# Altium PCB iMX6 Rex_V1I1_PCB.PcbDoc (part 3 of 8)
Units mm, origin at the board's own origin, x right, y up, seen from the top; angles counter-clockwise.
Board outline 70 x 40 mm, 12 copper layers (L1, L2, L3, L4, L5 (PWR), L6 (PWR), L7 (PWR), L8 (PWR), L9, L10, L11, L12), stack 1.566 mm thick; 473 components, 409 nets, 2294 pads, 1880 vias.
Unrouted connection lines stored in the file: 7.
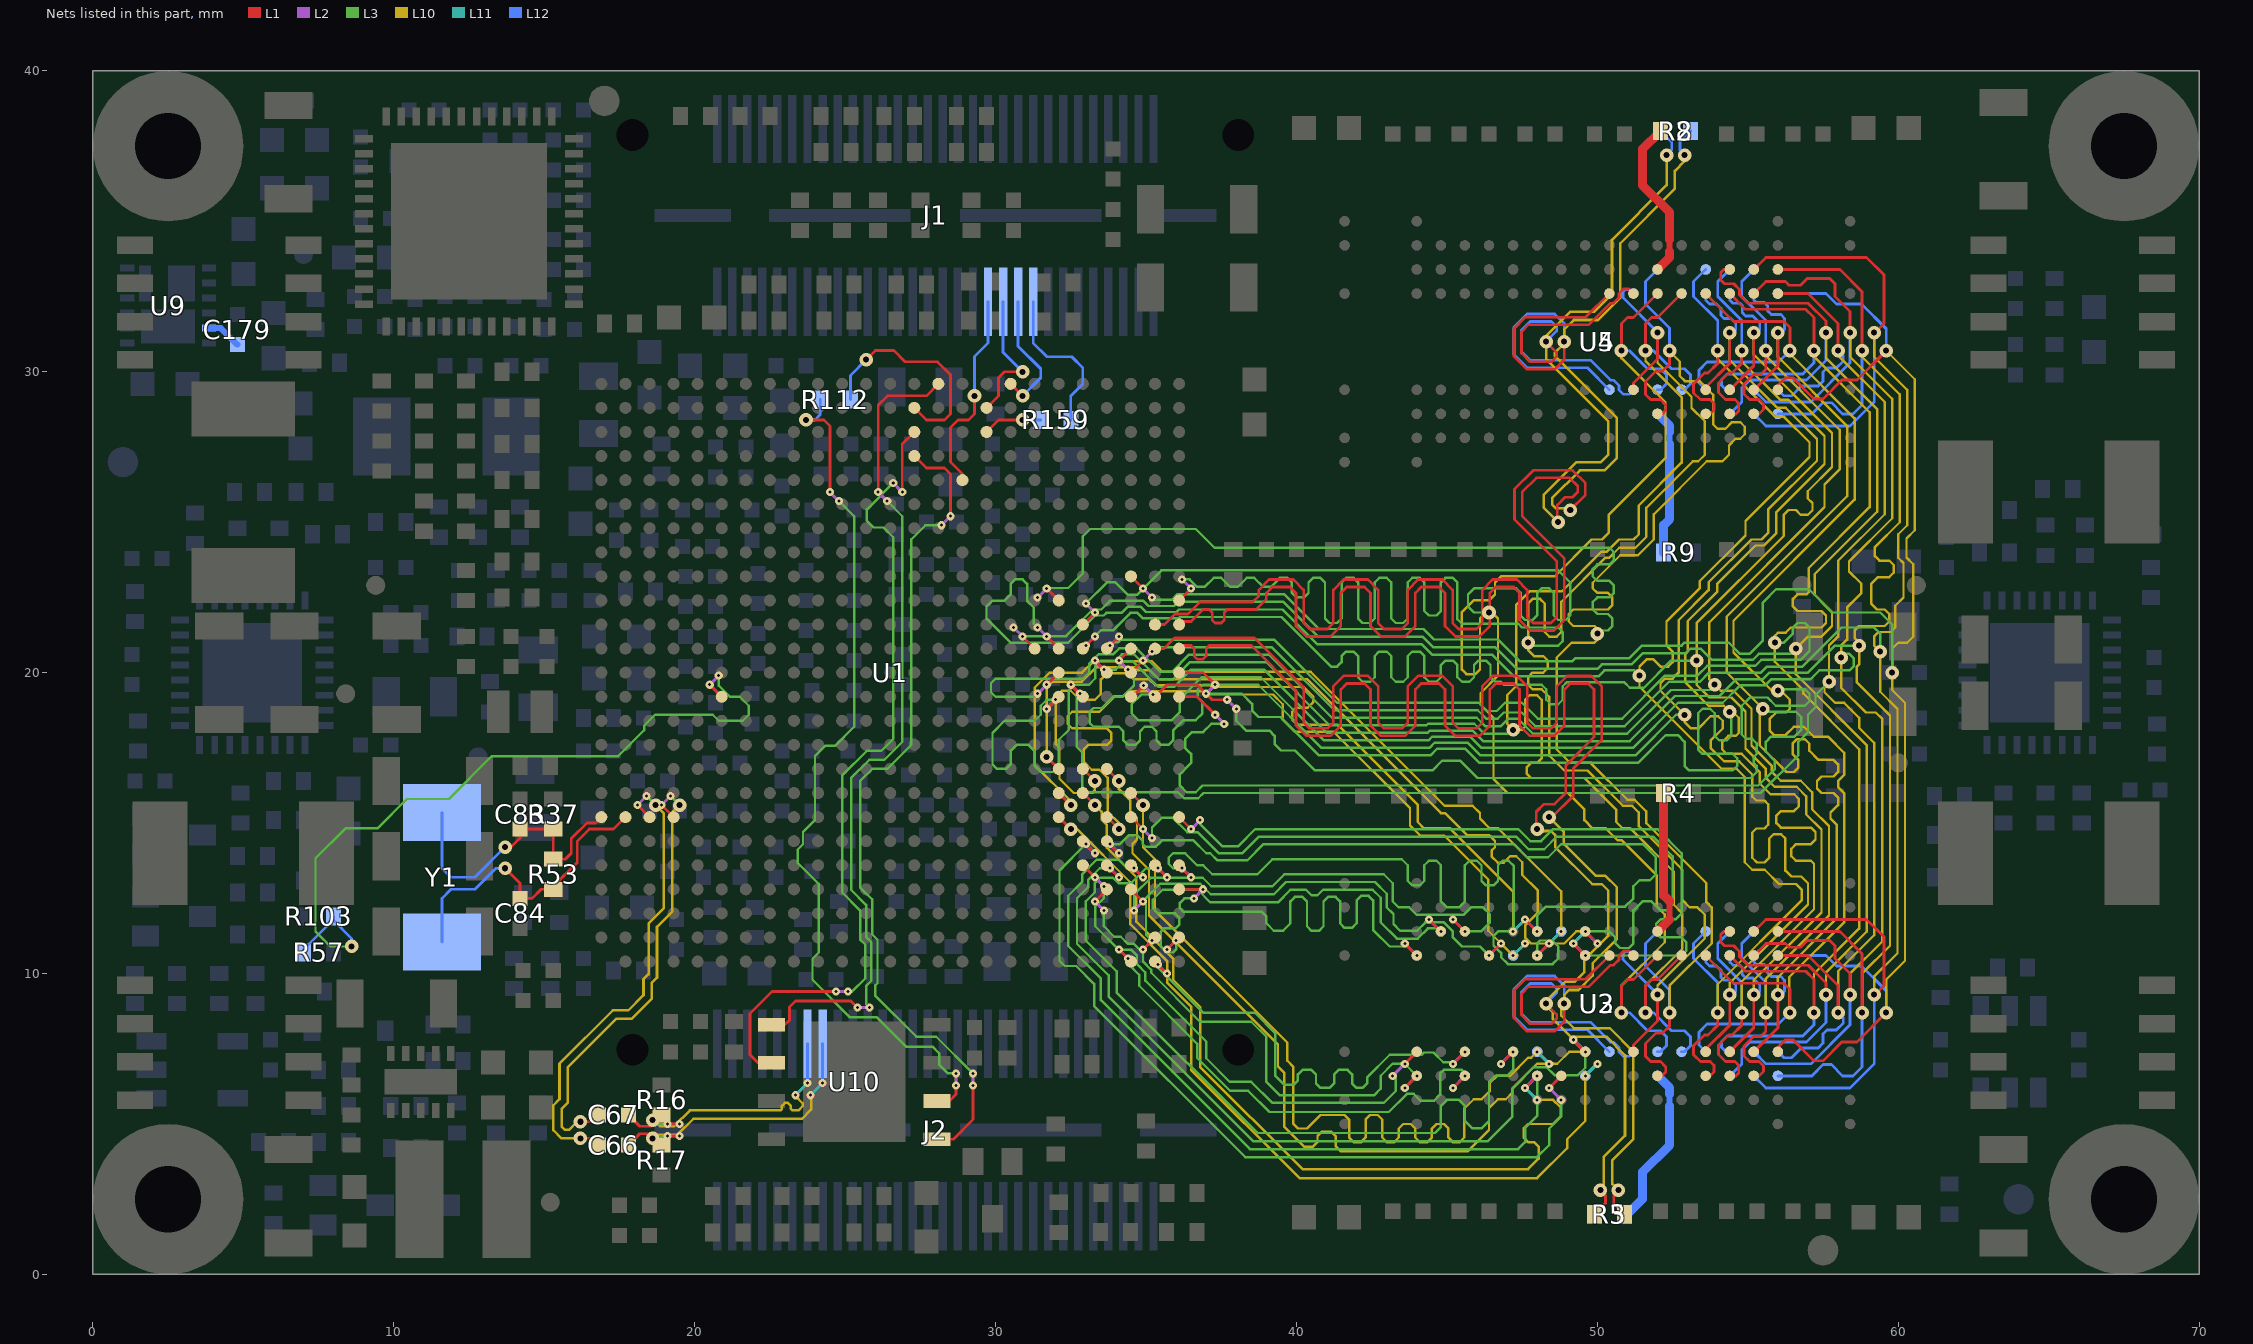
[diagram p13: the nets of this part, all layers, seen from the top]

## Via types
v1: diameter 0.45, hole 0.2, L1 to L12, tented both sides, 761 vias
v2: diameter 0.27, hole 0.1, L1 to L2, 305 vias
v3: diameter 0.27, hole 0.1, L2 to L3, 290 vias
v4: diameter 0.45, hole 0.2, L3 to L10, 196 vias
v5: diameter 0.27, hole 0.1, L11 to L12, 185 vias
v6: diameter 0.27, hole 0.1, L10 to L11, 142 vias
v7: diameter 0.45, hole 0.2, L3 to L10, tented both sides, 1 vias

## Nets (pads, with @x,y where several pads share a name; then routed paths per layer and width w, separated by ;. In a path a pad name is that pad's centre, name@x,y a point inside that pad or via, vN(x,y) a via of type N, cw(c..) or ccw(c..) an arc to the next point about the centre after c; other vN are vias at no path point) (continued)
BOOT_MODE1: R57.2 R103.1 U1.F12 | length 26.1
  L1 w0.093: v2(20.5,19.6) U1.F12@20.9,19.2
  L2 w0.1: v2(20.5,19.6) v3(20.8,19.9)
  L3 w0.08: v1(8.6,10.9) 7.9,10.9 7.4,11.4 7.4,13.83 8.395,14.825 9.455,14.825 10.43,15.8 11.831,15.8 13.256,17.225 17.461,17.225 18.325,18.089 18.325,18.238 18.687,18.6 20.6,18.6 20.8,18.4 21.6,18.4 21.8,18.6 21.8,18.9 21.5,19.2 21.17,19.2 20.8,19.57 v3(20.8,19.9)
  L12 w0.093: R57.2@7,10.7 7,10.8 R103.1@8,11.8 ; R103.1@8,11.9 R103.1@8,11.8 ; v1(8.6,10.9) 8.6,11.17 8,11.77 R103.1@8,11.8
CFF: C179.2 U9.11 | length 1.2
  L12 w0.2: U9.11@3.86,31.45 4.25,31.45 C179.2@4.8,30.9
CLK1_C_N: C66.1 U1.C7 | length 15.9
  L1 w0.09: v1(16.2,4.525) 16.575,4.525 C66.1@16.8,4.3 ; v2(18.1,15.6) U1.C7@18.5,15.2
  L2 w0.1: v2(18.1,15.6) v3(18.4,15.9)
  L3 w0.085: v3(18.4,15.9) v4(18.7,15.6)
  L10 w0.085: v1(16.2,4.525) 15.575,4.525 15.3,4.8 15.3,5.616 15.508,5.824 15.508,7.004 17.284,8.78 17.8,8.78 18.3,9.28 18.3,9.816 18.468,9.983 18.468,11.664 18.97,12.167 18.97,15.33 v4(18.7,15.6)
CLK1_C_P: C67.1 U1.D7 | length 15.8
  L1 w0.09: v1(16.2,5.075) 16.575,5.075 C67.1@16.8,5.3 ; v2(18.9,15.6) U1.D7@19.3,15.2
  L2 w0.1: v2(18.9,15.6) v3(19.2,15.9)
  L3 w0.085: v3(19.2,15.9) v4(19.5,15.6)
  L10 w0.085: v1(16.2,5.075) 16.096,5.075 15.826,4.805 15.691,4.805 15.58,4.916 15.58,5.5 15.788,5.708 15.788,6.888 17.4,8.5 17.916,8.5 18.58,9.164 18.58,9.7 18.748,9.867 18.748,11.548 19.25,12.051 19.25,15.35 ; 19.25,15.35 v4(19.5,15.6) 19.25,15.35
CLK1_N: C66.2 J2.46 R17.2 | length 11.1
  L1 w0.09: C66.2@17.8,4.3 18.175,4.675 18.525,4.675 R17.2@18.9,4.3 19.2,4.6 v2(19.5,4.6)
  L2 w0.1: v3(19.1,4.6) v2(19.5,4.6)
  L3 w0.085: v4(18.6,4.525) 18.675,4.6 v3(19.1,4.6)
  L10 w0.085: v4(18.6,4.525) 18.725,4.65 19.431,4.65 19.953,5.173 23.568,5.173 23.87,5.474 23.87,5.937 v6(23.85,5.957)
  L11 w0.1: v6(23.85,5.957) v5(24.25,6.358)
  L12 w0.09: v5(24.25,6.358) J2.46@24.25,7.67
CLK1_P: C67.2 J2.48 R16.2 | length 11.1
  L1 w0.09: C67.2@17.8,5.3 18.175,4.925 18.525,4.925 R16.2@18.9,5.3 19.2,5 v2(19.5,5)
  L2 w0.1: v3(19.1,5) v2(19.5,5)
  L3 w0.085: v4(18.6,5.125) 18.725,5 v3(19.1,5)
  L10 w0.085: v4(18.6,5.125) 18.654,5.125 18.849,4.93 19.315,4.93 19.838,5.453 22.853,5.453 22.9,5.5 22.9,5.6 23,5.7 23.1,5.7 23.2,5.6 23.2,5.5 23.247,5.453 23.453,5.453 23.59,5.59 23.59,5.69 23.35,5.931 v6(23.35,5.957)
  L11 w0.1: v6(23.35,5.957) v5(23.75,6.358)
  L12 w0.09: v5(23.75,6.358) J2.48@23.75,7.67
CPU_XTALI: C83.1 R37.1 R53.1 U1.A7 Y1.1 | length 10
  L1 w0.093: v1(13.7,14.2) 13.9,14.2 14.2,14.5 C83.1@14.2,14.8 R37.1@15.3,14.8 R53.1@15.3,13.8 15.7,13.8 15.9,14 15.9,14.483 16.417,15 16.7,15 U1.A7@16.9,15.2
  L12 w0.093: Y1.1@11.6,15.35 11.6,13.5 11.9,13.2 12.7,13.2 v1(13.7,14.2)
CPU_XTALO: C84.1 R53.2 U1.B7 Y1.2 | length 10.2
  L1 w0.093: v1(13.7,13.5) 14.2,13 14.2,12.6 C84.1@14.3,12.6 ; C84.1@14.2,12.5 14.6,12.5 14.9,12.8 R53.2@15.3,12.8 ; R53.2@15.3,12.9 16.1,13.7 16.1,14.4 16.5,14.8 17.3,14.8 U1.B7@17.7,15.2
  L12 w0.093: Y1.2@11.6,11.05 11.6,12.5 11.9,12.8 12.7,12.8 13.4,13.5 v1(13.7,13.5)
CSPI2_CLK: J1.17 R159.2 | length 5.3
  L12 w0.093: J1.17@31.25,32.33 31.25,30.955 31.705,30.5 32.53,30.5 32.9,30.13 32.9,29.6 32.5,29.2 R159.2@32.5,28.4
CSPI2_CLK_R: R159.1 U1.U23 | length 2
  L1 w0.093: U1.U23@29.7,28 30.1,28.4 v1(30.9,28.4)
  L12 w0.093: v1(30.9,28.4) R159.1@31.5,28.4
CSPI2_CS0: J1.19 U1.V25 | length 4.3
  L1 w0.093: U1.V25@30.5,29.6 v1(30.9,29.2)
  L12 w0.093: J1.19@30.75,32.33 30.75,30.85 31.5,30.1 31.5,29.8 v1(30.9,29.2)
CSPI2_MISO: J1.21 U1.U24 | length 4.6
  L1 w0.093: U1.U24@29.7,28.8 30.1,29.2 30.1,29.8 30.3,30 v1(30.9,30)
  L12 w0.093: J1.21@30.25,32.33 30.25,30.65 v1(30.9,30)
CSPI2_MOSI: J1.23 U1.T21 | length 6.8
  L1 w0.093: U1.T21@28.9,26.4 28.9,26.6 28.5,27 28.5,28.15 28.75,28.4 29.1,28.4 29.3,28.6 v1(29.3,29.2)
  L12 w0.093: v1(29.3,29.2) 29.3,30.505 29.75,30.955 J1.23@29.75,32.33
CSPI3_CLK: R112.2 U10.6 | length 29.7
  L1 w0.093: v1(23.7,28.4) 24.3,28.4 24.5,28.2 v2(24.5,26) ; U10.6@28.05,5.765 28.465,5.765 28.688,5.988 v2(28.688,6.28)
  L2 w0.1: v2(24.5,26) v3(24.8,25.7) ; v2(28.688,6.28) v3(28.688,6.68)
  L3 w0.08: v3(24.8,25.7) 25.3,25.2 25.3,18.2 24.675,17.575 24.345,17.575 24,17.23 24,15.1 23.6,14.7 23.6,14.297 23.425,14.122 23.425,13.678 24.125,12.978 24.125,10.7 23.915,10.49 23.915,9.795 25.168,8.543 26.057,8.543 27.027,7.573 27.905,7.573 28.125,7.353 28.125,6.975 28.42,6.68 v3(28.688,6.68)
  L12 w0.093: v1(23.7,28.4) 24,28.4 24.175,28.575 R112.2@24.175,29.075
CSPI3_CLK_R: R112.1 U1.P24 | length 7.6
  L1 w0.093: v1(25.7,30.4) 26.005,30.705 26.625,30.705 27,30.33 28.07,30.33 28.5,29.9 28.5,28.6 28.3,28.4 27.7,28.4 U1.P24@27.3,28.8
  L12 w0.093: R112.1@25.175,29.075 25.175,29.875 v1(25.7,30.4)
CSPI3_CS2: U1.R25 U10.1 | length 28
  L1 w0.093: U10.1@22.55,8.305 23.005,8.305 23.15,8.45 23.15,8.893 23.35,9.093 25.188,9.093 v2(25.413,8.868) ; v2(26.1,26) 26.1,28.895 26.405,29.2 27.7,29.2 U1.R25@28.1,29.6
  L2 w0.1: v2(25.413,8.868) v3(25.812,8.868) ; v2(26.1,26) v3(26.4,25.7)
  L3 w0.08: v3(25.812,8.868) 25.7,8.98 25.7,9.587 25.875,9.762 25.875,11.038 25.7,11.213 25.7,12.283 25.2,12.783 25.2,16.5 25.8,17.1 26.3,17.1 26.9,17.7 26.9,25.2 v3(26.4,25.7)
CSPI3_MISO: U1.P23 U10.2 | length 27.8
  L1 w0.093: U10.2@22.55,7.035 22.107,7.035 21.84,7.302 21.84,8.667 22.573,9.4 v2(24.7,9.4) ; v2(26.9,26) 26.9,27.6 U1.P23@27.3,28
  L2 w0.1: v2(24.7,9.4) v3(25.1,9.4) ; v3(26.6,26.3) v2(26.9,26)
  L3 w0.08: v3(25.1,9.4) 25.23,9.4 25.675,9.845 25.675,10.955 25.5,11.13 25.5,12.1 24.9,12.7 24.9,16.583 25.717,17.4 26.201,17.4 26.6,17.799 26.6,24.5 26.275,24.825 25.945,24.825 25.725,25.045 25.725,25.428 26.597,26.3 v3(26.6,26.3)
CSPI3_MOSI: U1.P22 U10.5 | length 28.2
  L1 w0.093: U1.P22@27.3,27.2 27.7,26.8 28.3,26.8 28.5,26.6 v2(28.5,25.2) ; U10.5@28.05,4.495 28.6,4.495 29.25,5.145 v2(29.25,6.28)
  L2 w0.1: v3(28.2,24.9) v2(28.5,25.2) ; v2(29.25,6.28) v3(29.25,6.68)
  L3 w0.08: v3(28.2,24.9) 27.67,24.9 27.2,24.43 27.2,17.6 26.4,16.8 25.9,16.8 25.5,16.4 25.5,12.866 25.9,12.466 25.9,11.3 26.075,11.125 26.075,9.679 25.998,9.602 25.998,9.272 27.37,7.9 28.03,7.9 v3(29.25,6.68)
DRAM0_ZQ: R4.2 U2.L8 | length 4.8
  L1 w0.2: 52.4,11.8 52.4,12.401
  L1 w0.3: U2.L8@52,11.4 52.4,11.8 ; R4.2@52.2,16 52.2,12.601 52.4,12.401
DRAM1_ZQ: R5.2 U3.L8 | length 5.4
  L12 w0.2: 52.4,5.599 52.4,6.001
  L12 w0.3: R5.2@50.9,2 51,2 51.5,2.5 51.5,3.4 52.4,4.3 52.4,5.599 ; U3.L8@52,6.6 52.4,6.2 52.4,6.001
DRAM2_ZQ: R8.2 U4.L8 | length 5.4
  L1 w0.2: 52.4,33.999 52.4,34.401
  L1 w0.3: U4.L8@52,33.4 52.4,33.8 52.4,33.999 ; R8.2@52.1,38 51.5,37.4 51.5,36.2 52.4,35.3 52.4,34.401
DRAM3_ZQ: R9.2 U5.L8 | length 4.8
  L12 w0.2: 52.4,27.599 52.4,28.001
  L12 w0.3: U5.L8@52,28.6 52.4,28.2 52.4,28.001 ; R9.2@52.2,24 52.2,24.9 52.4,25.1 52.4,27.599
DRAM_A0: U1.AC14 U2.N3 U3.N3 U4.N3 U5.N3 | length 70.8
  L1 w0.093: v2(34.1,20.4) U1.AC14@34.5,20.8 ; U2.N3@53.6,7.4 53.6,7.483 54.4,8.283 v1(54.4,9.3) ; U4.N3@53.6,29.4 53.6,29.483 54.4,30.283 v1(54.4,31.3)
  L2 w0.1: v2(34.1,20.4) v3(34.4,20.1)
  L3 w0.08: v3(34.4,20.1) 34.6,19.9 34.6,19.57 34.23,19.2 33.903,19.2 33.528,18.825 33.25,18.825 33.125,18.7 33.125,18.325 33.25,18.2 34.1,18.2 34.25,18.05 34.25,17.75 34.4,17.6 34.65,17.6 34.8,17.75 34.8,18.05 34.95,18.2 35.2,18.2 35.35,18.05 35.35,17.75 35.5,17.6 35.75,17.6 35.9,17.75 35.9,18.083 36.242,18.425 36.655,18.425 36.875,18.645 36.875,19.022 36.715,19.182 36.715,19.418 36.897,19.6 38.73,19.6 40.83,17.5 44.421,17.5 44.596,17.675 45.687,17.675 46.112,17.25 51.267,17.25 52.617,18.6 v4(52.9,18.6)
  L10 w0.08: v1(54.4,9.3) 54.4,9.691 57,12.291 57,13 56.775,13.225 56.448,13.225 56.25,13.423 56.25,14.488 56.109,14.629 55.859,14.629 55.709,14.479 55.709,13.841 55.559,13.691 55.309,13.691 55.15,13.85 55.15,14.689 55.28,14.82 55.55,14.82 55.675,14.945 55.675,15.625 55.55,15.75 55.28,15.75 55.15,15.88 55.15,16.616 54.716,17.05 54.216,17.05 53.766,17.5 53.766,17.75 54.166,18.15 54.166,18.4 54.016,18.55 53.766,18.55 53.366,18.15 53.116,18.15 52.9,18.366 v4(52.9,18.6) 52.1,19.4 52.1,19.65 52.25,19.8 52.5,19.8 52.7,20 52.7,21.742 53.7,22.742 53.7,23.004 55.121,24.425 55.455,24.425 55.675,24.645 55.675,25.418 57.3,27.043 57.3,27.762 56.262,28.8 55.993,28.8 54.4,30.393 v1(54.4,31.3)
  L12 w0.093: U3.N3@53.6,10.6 53.6,10.383 53.729,10.254 53.963,10.254 54.109,10.109 54.109,9.874 54.208,9.775 54.442,9.775 54.6,9.617 54.6,9.4 54.5,9.3 v1(54.4,9.3) ; U5.N3@53.6,32.6 53.6,32.383 53.729,32.254 53.963,32.254 54.109,32.109 54.109,31.874 54.208,31.775 54.442,31.775 54.6,31.617 54.6,31.4 54.5,31.3 v1(54.4,31.3)
DRAM_A1: U1.AB14 U2.P7 U3.P7 U4.P7 U5.P7 | length 74
  L1 w0.093: U1.AB14@33.7,20.8 v2(34.1,21.2) ; U2.P7@54.4,10.6 54.925,10.075 56.925,10.075 57.2,9.8 v1(57.2,8.7) ; U4.P7@54.4,32.6 54.925,32.075 56.925,32.075 57.2,31.8 v1(57.2,30.7)
  L2 w0.1: v3(33.8,20.9) v2(34.1,21.2)
  L3 w0.08: v3(33.8,20.9) 33.907,21.007 34.076,21.007 34.169,21.1 39.252,21.1 41.352,19 46.059,19 46.334,18.725 46.655,18.725 46.93,19 47.496,19 48.021,18.475 50.828,18.475 52.253,19.9 53.33,19.9 53.655,20.225 55.246,20.225 55.446,20.425 56.755,20.425 57.05,20.72 57.05,21.5 56.9,21.65 56.65,21.65 56.5,21.5 56.5,21.3 56.2,21 v4(55.9,21)
  L10 w0.08: v1(57.2,8.7) 57.2,9.993 58.7,11.493 58.7,17.454 56.85,19.304 56.85,19.413 55.9,20.363 v4(55.9,21) 55.9,21.225 56,21.325 56.255,21.325 56.43,21.5 57.45,21.5 57.6,21.65 57.6,21.9 57.45,22.05 56.65,22.05 56.5,22.2 56.5,22.45 56.65,22.6 56.95,22.6 57.025,22.675 57.025,23.475 59.05,25.5 59.05,28.657 57.2,30.507 v1(57.2,30.7)
  L12 w0.093: U3.P7@54.4,7.4 54.275,7.4 54.125,7.55 54.125,7.742 54.308,7.925 56.825,7.925 57.2,8.3 v1(57.2,8.7) ; U5.P7@54.4,29.4 54.275,29.4 54.125,29.55 54.125,29.742 54.308,29.925 56.825,29.925 57.2,30.3 v1(57.2,30.7)
DRAM_A2: U1.AA14 U2.P3 U3.P3 U4.P3 U5.P3 | length 68.5
  L1 w0.093: U1.AA14@32.9,20.8 v2(33.3,21.2) ; U2.P3@54.4,7.4 55.2,8.2 v1(55.2,9.3) ; U4.P3@54.4,29.4 55.2,30.2 v1(55.2,31.3)
  L2 w0.1: v3(33,20.9) v2(33.3,21.2)
  L3 w0.08: v3(33,20.9) 33.515,21.415 33.918,21.415 34.315,21.812 34.315,21.818 34.482,21.985 34.718,21.985 34.888,21.815 36.094,21.815 36.129,21.85 39.501,21.85 41.151,20.2 41.351,20.2 41.5,20.349 41.5,20.549 41.651,20.699 41.901,20.699 42.051,20.549 42.051,19.85 42.201,19.7 42.451,19.7 42.601,19.85 42.601,20.549 ; 42.6,20.55 42.749,20.699 43.001,20.699 43.151,20.549 43.151,19.85 43.301,19.7 43.551,19.7 43.701,19.85 43.701,20.551 43.849,20.699 44.101,20.699 44.251,20.549 44.251,19.85 44.401,19.7 44.651,19.7 44.801,19.85 44.801,20.249 44.949,20.399 45.201,20.399 45.351,20.249 45.351,19.85 45.501,19.7 45.751,19.7 45.901,19.85 45.901,20.25 46.051,20.4 46.301,20.4 46.451,20.25 46.451,19.851 46.601,19.701 46.782,19.701 46.883,19.6 48.15,19.6 48.3,19.45 48.3,19.099 48.449,18.95 48.7,18.95 48.85,19.1 48.85,19.55 48.975,19.675 50.9,19.675 51.075,19.5 51.55,19.5 52.45,20.4 v4(53.3,20.4)
  L10 w0.08: v1(55.2,9.3) 55.2,9.784 57.45,12.034 57.45,14.783 56.943,15.289 56.943,15.889 56.626,16.207 55.893,16.207 55.6,16.5 55.6,16.8 54.925,17.475 54.925,18.705 54.455,19.175 53.725,19.175 53.3,19.6 v4(53.3,20.4) 53.3,21.65 56.2,24.55 56.2,25.256 56.35,25.406 56.6,25.406 56.756,25.25 57,25.25 57.15,25.4 57.15,25.638 56.994,25.794 56.994,26.029 57.8,26.835 57.8,27.97 55.2,30.57 v1(55.2,31.3)
  L12 w0.093: U3.P3@54.4,10.6 54.4,10.383 54.504,10.279 54.738,10.279 54.816,10.201 54.816,9.967 54.929,9.854 55.163,9.854 55.4,9.617 55.4,9.4 55.3,9.3 v1(55.2,9.3) ; U5.P3@54.4,32.6 54.4,32.383 54.504,32.279 54.738,32.279 54.816,32.201 54.816,31.967 54.929,31.854 55.163,31.854 55.4,31.617 55.4,31.4 55.3,31.3 v1(55.2,31.3)
DRAM_A3: U1.Y14 U2.N2 U3.N2 U4.N2 U5.N2 | length 72.4
  L1 w0.093: v2(31.7,21.2) U1.Y14@32.1,20.8 ; U2.N2@53.6,6.6 53.75,6.6 53.875,6.725 53.875,6.95 53.75,7.075 53.425,7.075 53.2,7.3 53.2,7.6 53.563,7.963 53.68,7.963 54,8.283 v1(54,8.7) ; U4.N2@53.6,28.6 53.75,28.6 53.875,28.725 53.875,28.95 53.75,29.075 53.425,29.075 53.2,29.3 53.2,29.6 53.563,29.963 53.68,29.963 54,30.283 v1(54,30.7)
  L2 w0.1: v3(31.4,21.5) v2(31.7,21.2)
  L3 w0.08: v3(31.4,21.5) 31.275,21.625 31.275,22.155 31.051,22.38 31.051,22.949 30.901,23.099 30.651,23.099 30.501,22.949 30.501,22.601 30.286,22.386 29.886,22.386 29.7,22.2 29.7,21.8 30.5,21 32.414,21 33.314,21.9 33.597,21.9 33.682,21.985 34.185,21.985 34.385,22.185 34.829,22.185 34.999,22.015 36.011,22.015 36.096,22.1 39.534,22.1 40.684,20.95 44.154,20.95 44.504,20.6 46.5,20.6 47.225,19.875 50.033,19.875 50.233,20.075 51.225,20.075 v4(51.4,19.9)
  L10 w0.08: v1(54,8.7) 54,9.645 56.8,12.445 56.8,12.78 56.605,12.975 56.038,12.975 55.563,13.45 55.15,13.45 54.9,13.7 54.9,16.533 54.633,16.8 54.133,16.8 51.4,19.533 v4(51.4,19.9) 51.4,20.2 51.65,20.45 51.85,20.45 52.1,20.2 52.35,20.2 52.5,20.35 52.5,20.7 52.3,20.9 52.3,21.7 53.4,22.8 53.4,23.037 54.925,24.562 54.925,25.038 57.05,27.163 57.05,27.659 56.209,28.5 55.926,28.5 54,30.426 v1(54,30.7)
  L12 w0.093: U3.N2@53.6,11.4 53.2,11 53.2,10.5 54,9.7 v1(54,8.7) ; U5.N2@53.6,33.4 53.2,33 53.2,32.5 54,31.7 v1(54,30.7)
DRAM_A4: U1.W14 U2.P8 U3.P8 U4.P8 U5.P8 | length 75.9
  L1 w0.093: v2(30.9,21.2) U1.W14@31.3,20.8 ; U2.P8@54.4,11.4 54.2,11.4 54.1,11.3 54.1,11.05 54.225,10.925 54.535,10.925 54.725,10.735 54.725,10.558 55.008,10.275 57.008,10.275 57.6,9.683 v1(57.6,9.3) ; U4.P8@54.4,33.4 54.2,33.4 54.1,33.3 54.1,33.05 54.225,32.925 54.535,32.925 54.725,32.735 54.725,32.558 55.008,32.275 57.008,32.275 57.6,31.683 v1(57.6,31.3)
  L2 w0.1: v3(30.6,21.5) v2(30.9,21.2)
  L3 w0.08: v3(30.6,21.5) 30.885,21.215 32.346,21.215 33.231,22.1 33.514,22.1 33.799,22.385 34.912,22.385 35.082,22.215 35.928,22.215 36.063,22.35 39.566,22.35 40.716,21.2 44.187,21.2 44.537,20.85 46.6,20.85 47.325,20.125 50,20.125 50.15,20.275 51.141,20.275 51.516,20.65 52.95,20.65 53.1,20.8 53.43,20.8 53.805,20.425 55.163,20.425 55.363,20.625 56.425,20.625 v4(56.6,20.8)
  L10 w0.08: v1(57.6,9.3) 57.6,10.039 58.95,11.389 58.95,17.596 56.6,19.946 v4(56.6,20.8) 57,21.2 57.45,21.2 57.8,21.55 57.8,22.02 57.225,22.595 57.225,23.275 59.3,25.35 59.3,27.5 59.3,28.761 57.6,30.461 v1(57.6,31.3)
  L12 w0.093: U3.P8@54.4,6.6 54.8,7 54.8,7.46 55.065,7.725 56.95,7.725 57.6,8.375 v1(57.6,9.3) ; U5.P8@54.4,28.6 54.8,29 54.8,29.46 55.065,29.725 56.95,29.725 57.6,30.375 v1(57.6,31.3)
DRAM_A5: U1.AE13 U2.P2 U3.P2 U4.P2 U5.P2 | length 73.2
  L1 w0.093: U1.AE13@36.1,20 36.9,20 v2(37.3,19.6) ; U2.P2@54.4,6.6 54.6,6.6 54.7,6.7 54.7,6.95 54.575,7.075 54.265,7.075 54.025,7.315 54.025,7.625 54.363,7.963 54.48,7.963 54.8,8.283 v1(54.8,8.7) ; U4.P2@54.4,28.6 54.6,28.6 54.7,28.7 54.7,28.95 54.575,29.075 54.265,29.075 54.025,29.315 54.025,29.625 54.363,29.963 54.48,29.963 54.8,30.283 v1(54.8,30.7)
  L2 w0.1: v3(37,19.3) v2(37.3,19.6)
  L3 w0.08: v3(37,19.3) 37.003,19.303 38.183,19.303 38.525,18.961 38.525,18.745 38.745,18.525 39.473,18.525 40.748,17.25 44.454,17.25 44.679,17.475 45.604,17.475 46.079,17 51.35,17 52.275,17.925 52.675,17.925 52.9,17.7 52.9,16.9 53.05,16.75 54.5,16.75 54.65,16.9 54.65,17.15 54.5,17.3 53.5,17.3 53.35,17.45 53.35,18.65 53.5,18.8 53.75,18.8 53.9,18.65 53.9,17.9 54.05,17.75 54.3,17.75 54.45,17.9 54.45,18.65 v4(54.4,18.7)
  L10 w0.08: v1(54.8,8.7) 54.8,9.738 57.2,12.138 57.2,13.65 57.1,13.75 56.6,13.75 56.45,13.9 56.45,14.15 56.6,14.3 57.1,14.3 57.25,14.45 57.25,14.7 57.1,14.85 56.1,14.85 55.95,15 55.95,15.25 56.1,15.4 56.537,15.4 56.693,15.557 56.693,15.807 56.543,15.957 55.757,15.957 55.4,16.313 55.4,16.7 54.8,17.3 54.3,17.3 54.15,17.45 54.15,17.7 54.35,17.9 54.6,17.9 54.7,18 54.7,18.5 54.5,18.7 v4(54.4,18.7) 54.2,18.9 53.7,18.9 52.925,19.675 52.925,20.63 53,20.705 53,21.709 53.991,22.7 53.991,22.962 55.254,24.225 55.538,24.225 55.95,24.637 55.95,25.339 57.55,26.939 57.55,27.866 56.341,29.075 56.071,29.075 54.8,30.346 v1(54.8,30.7)
  L12 w0.093: U3.P2@54.4,11.4 54,11 54,10.5 54.8,9.7 v1(54.8,8.7) ; U5.P2@54.4,33.4 54,33 54,32.5 54.8,31.7 v1(54.8,30.7)
DRAM_A6: U1.AC13 U2.R8 U3.R8 U4.R8 U5.R8 | length 79.7
  L1 w0.093: U1.AC13@34.5,20 v2(34.9,20.4) ; U2.R8@55.2,11.4 55.6,11.8 58.95,11.8 59.525,11.225 59.525,9.6 59.225,9.3 v1(59.2,9.3) ; U4.R8@55.2,33.4 55.6,33.8 58.95,33.8 59.525,33.225 59.525,31.6 59.225,31.3 v1(59.2,31.3)
  L2 w0.1: v2(34.9,20.4) v3(35.2,20.7)
  L3 w0.08: v3(35.2,20.7) 35.35,20.85 39.169,20.85 41.269,18.75 46.026,18.75 46.301,18.475 46.688,18.475 46.888,18.675 47.488,18.675 47.938,18.225 50.911,18.225 52.386,19.7 53.413,19.7 53.713,20 55.434,20 55.634,20.2 56.813,20.2 58.113,21.5 59.2,21.5 59.4,21.3 v4(59.4,20.7)
  L10 w0.08: v1(59.2,9.3) 59.2,9.9 59.975,10.675 59.975,18.791 59.4,19.366 v4(59.4,20.7) 59.2,20.9 59.2,21.2 59.35,21.35 59.75,21.35 59.9,21.5 59.9,22.225 60.175,22.5 60.175,23.645 60,23.82 60,24.6 60.3,24.9 60.3,29.399 59.2,30.499 v1(59.2,31.3)
  L12 w0.093: U3.R8@55.2,6.6 55.6,6.2 58.4,6.2 59.2,7 v1(59.2,9.3) ; U5.R8@55.2,28.6 55.6,28.2 58.4,28.2 59.2,29 v1(59.2,31.3)
DRAM_A7: U1.Y13 U2.R2 U3.R2 U4.R2 U5.R2 | length 71
  L1 w0.093: v2(31.7,19.6) U1.Y13@32.1,20 ; U2.R2@55.2,6.6 55.375,6.6 55.525,6.75 55.525,6.925 55.375,7.075 55.065,7.075 54.875,7.265 54.875,7.592 55.191,7.909 55.426,7.909 55.6,8.083 v1(55.6,8.7) ; U4.R2@55.2,28.6 55.375,28.6 55.525,28.75 55.525,28.925 55.375,29.075 55.065,29.075 54.875,29.265 54.875,29.592 55.191,29.909 55.426,29.909 55.6,30.083 v1(55.6,30.7)
  L2 w0.1: v3(31.4,19.3) v2(31.7,19.6)
  L3 w0.08: v3(31.4,19.3) 31.3,19.2 30,19.2 29.85,19.35 29.85,19.65 30,19.8 32.9,19.8 33.115,20.015 33.115,20.301 33.429,20.615 33.918,20.615 34.11,20.807 34.69,20.807 35.472,20.025 35.859,20.025 36.434,20.6 39.087,20.6 41.187,18.5 45.993,18.5 46.268,18.225 46.795,18.225 47.045,18.475 47.355,18.475 47.855,17.975 50.994,17.975 52.444,19.425 53.725,19.425 v4(53.9,19.6)
  L10 w0.08: v1(55.6,8.7) 55.6,9.83 57.7,11.93 57.7,14.9 57.143,15.457 57.143,16.022 56.759,16.407 56.093,16.407 55.8,16.7 55.8,16.9 55.125,17.575 55.125,18.8 54.525,19.4 54.1,19.4 v4(53.9,19.6) 53.725,19.775 53.725,21.675 57.55,25.5 57.55,26.253 58.05,26.753 58.05,28.073 55.6,30.523 v1(55.6,30.7)
  L12 w0.093: U3.R2@55.2,11.4 54.8,11 54.8,10.5 55.6,9.7 v1(55.6,8.7) ; U5.R2@55.2,33.4 54.8,33 54.8,32.5 55.6,31.7 v1(55.6,30.7)
DRAM_A8: U1.AB13 U2.T8 U3.T8 U4.T8 U5.T8 | length 75.5
  L1 w0.093: v2(33.3,20.4) U1.AB13@33.7,20 ; U2.T8@56,11.4 58.06,11.4 58.8,10.66 v1(58.8,8.7) ; U4.T8@56,33.4 58.06,33.4 58.8,32.66 v1(58.8,30.7)
  L2 w0.1: v2(33.3,20.4) v3(33.6,20.1)
  L3 w0.08: v3(33.6,20.1) 33.997,20.1 34.282,20.385 34.546,20.385 35.406,19.525 35.925,19.525 36.5,20.1 38.921,20.1 41.021,18 44.355,18 44.43,18.075 45.852,18.075 46.202,17.725 51.076,17.725 52.576,19.225 54.055,19.225 54.605,19.775 55.492,19.775 55.717,20 57,20 57.9,20.9 v4(58.7,20.9)
  L10 w0.08: v1(58.8,8.7) 58.8,10 59.725,10.925 59.725,18.575 58.625,19.675 58.625,20.2 58.7,20.275 v4(58.7,20.9) 58.7,21 58.55,21.15 58.55,21.4 58.7,21.55 59.55,21.55 59.7,21.7 59.7,21.95 59.55,22.1 59.3,22.1 59.1,22.3 59.1,22.95 59.325,23.175 59.7,23.175 59.85,23.325 59.85,23.575 59.7,23.725 59.375,23.725 59.225,23.875 59.225,24.175 60.05,25 60.05,29.25 58.8,30.5 v1(58.8,30.7)
  L12 w0.093: U3.T8@56,6.6 57.126,6.6 57.5,6.974 57.776,6.974 58.15,6.6 58.5,6.6 58.8,6.9 v1(58.8,8.7) ; U5.T8@56,28.6 57.126,28.6 57.5,28.974 57.776,28.974 58.15,28.6 58.5,28.6 58.8,28.9 v1(58.8,30.7)
DRAM_A9: U1.AE12 U2.R3 U3.R3 U4.R3 U5.R3 | length 69.7
  L1 w0.093: U1.AE12@36.1,19.2 36.7,19.2 v2(37.3,18.6) ; U2.R3@55.2,7.4 56,8.2 v1(56,9.3) ; U4.R3@55.2,29.4 56,30.2 v1(56,31.3)
  L2 w0.1: v2(37.3,18.6) v3(37.6,18.3)
  L3 w0.08: v3(37.6,18.3) 37.175,18.3 36.9,18.025 36.525,18.025 36.3,17.8 36.3,17.5 36.5,17.3 36.5,17 36.125,16.625 36.125,16.245 36.345,16.025 36.655,16.025 36.88,16.25 55.35,16.25 55.9,16.8 55.9,17.07 55.6,17.37 55.6,17.7 55.775,17.875 56.55,17.875 56.775,18.1 56.775,18.525 56.6,18.7 55.6,18.7 v4(55.5,18.8)
  L10 w0.08: v1(56,9.3) 56,9.877 57.95,11.827 57.95,14.95 57.75,15.15 57.75,15.35 58,15.6 58,15.85 57.85,16 57.45,16 57.3,16.15 57.3,16.4 57.45,16.55 57.85,16.55 58,16.7 58,16.95 57.85,17.1 57.35,17.1 57.041,17.409 57.041,17.641 56.891,17.791 56.641,17.791 56.491,17.641 56.491,17.291 56.683,17.1 56.683,16.85 56.533,16.7 56.283,16.7 55.4,17.583 55.4,18.7 v4(55.5,18.8) 54.3,20 54.3,21.863 58.3,25.863 58.3,28.199 56,30.499 v1(56,31.3)
  L12 w0.093: U3.R3@55.2,10.6 55.2,10.383 55.283,10.3 55.55,10.3 55.663,10.188 55.663,10.02 55.783,9.9 56.1,9.9 56.225,9.775 56.225,9.4 56.125,9.3 v1(56,9.3) ; U5.R3@55.2,32.6 55.2,32.383 55.283,32.3 55.55,32.3 55.663,32.188 55.663,32.02 55.783,31.9 56.1,31.9 56.225,31.775 56.225,31.4 56.125,31.3 v1(56,31.3)
DRAM_A10: U1.AA15 U2.L7 U3.L7 U4.L7 U5.L7 | length 73.3
  L1 w0.093: U1.AA15@32.9,21.6 v2(33.3,22) ; v1(50.8,8.7) 50.8,9.6 51,9.8 51.2,9.8 U2.L7@52,10.6 ; v1(50.8,30.7) 50.8,31.6 51,31.8 51.2,31.8 U4.L7@52,32.6
  L2 w0.1: v3(33,22.3) v2(33.3,22)
  L3 w0.08: v3(33,22.3) 33.7,23 33.985,23 34.4,22.585 34.698,22.585 35.513,23.4 48.7,23.4 49.1,23 49.1,21.9 48.95,21.75 48.7,21.75 48.55,21.9 48.55,22.65 48.4,22.8 48.15,22.8 48,22.65 48,21.9 47.85,21.75 47.6,21.75 47.45,21.9 47.45,22.65 47.3,22.8 45.9,22.8 45.7,22.6 45.7,22.2 45.9,22 v4(46.4,22)
  L10 w0.08: v1(50.8,8.7) 50.8,9.6 52.24,11.04 52.24,11.964 51.97,12.235 51.97,13.275 50.82,14.425 50.679,14.425 50.279,14.825 49.845,14.825 49.57,15.1 49.57,15.455 49.025,16 47.017,16 46.55,16.467 46.55,18.5 46.125,18.925 46.125,19.325 46.7,19.9 46.7,21.8 46.5,22 v4(46.4,22) 46.3,22 46.1,21.8 46.1,20.1 45.95,19.95 45.65,19.95 45.5,20.1 45.5,22.017 45.883,22.4 46.4,22.4 46.6,22.6 46.6,23 46.8,23.2 48.583,23.2 49.808,24.425 50.155,24.425 50.375,24.645 50.375,25.242 52.267,27.134 52.267,28.987 50.8,30.454 v1(50.8,30.7)
  L12 w0.093: v1(50.8,8.7) 51.07,8.7 51.67,8.1 52.1,8.1 52.3,7.9 52.3,7.6 52.1,7.4 U3.L7@52,7.4 ; v1(50.8,30.7) 51.07,30.7 51.67,30.1 52.1,30.1 52.3,29.9 52.3,29.6 52.1,29.4 U5.L7@52,29.4
DRAM_A11: U1.AC12 U2.R7 U3.R7 U4.R7 U5.R7 | length 74.5
  L1 w0.093: U1.AC12@34.525,19.175 v2(34.925,19.575) ; U2.R7@55.2,10.6 55.6,11 56.25,11 56.375,10.875 56.75,10.875 56.975,11.1 57.725,11.1 57.9,10.925 57.9,10.5 58.4,10 v1(58.4,9.3) ; U4.R7@55.2,32.6 55.6,33 56.25,33 56.375,32.875 56.75,32.875 56.975,33.1 57.725,33.1 57.9,32.925 57.9,32.5 58.4,32 v1(58.4,31.3)
  L2 w0.1: v2(34.925,19.575) v3(35.225,19.275)
  L3 w0.08: v3(35.225,19.275) 34.845,19.275 34.525,18.955 34.525,18.645 34.745,18.425 35.855,18.425 36.125,18.695 36.125,19.125 36.85,19.85 38.813,19.85 40.913,17.75 44.388,17.75 44.513,17.875 45.77,17.875 46.145,17.5 51.184,17.5 52.684,19 54.17,19 54.745,19.575 55.575,19.575 55.775,19.775 57.075,19.775 57.375,20.075 58.375,20.075 58.525,20.225 58.525,20.475 58.375,20.625 58.225,20.625 v4(58.1,20.5)
  L10 w0.08: v1(58.4,9.3) 58.4,10 59.475,11.075 59.475,18.455 59.255,18.675 58.925,18.675 58.1,19.5 v4(58.1,20.5) 58.1,20.9 58.3,21.1 58.3,22.17 58.775,22.645 58.775,22.955 58.365,23.365 58.365,23.699 59.8,25.134 59.8,29.099 58.4,30.499 v1(58.4,31.3)
  L12 w0.093: U3.R7@55.2,7.4 55.6,7 57.1,7 58.4,8.3 v1(58.4,9.3) ; U5.R7@55.2,29.4 55.6,29 57.1,29 58.4,30.3 v1(58.4,31.3)
DRAM_A12: U1.AD12 U2.N7 U3.N7 U4.N7 U5.N7 | length 74
  L1 w0.093: U1.AD12@35.3,19.2 35.7,19.6 36.7,19.6 37.2,19.1 v2(37.7,19.1) ; U2.N7@53.6,10.6 54.525,9.675 56.2,9.675 56.4,9.475 v1(56.4,8.7) ; U4.N7@53.6,32.6 54.525,31.675 56.2,31.675 56.4,31.475 v1(56.4,30.7)
  L2 w0.1: v2(37.7,19.1) v3(38,18.8)
  L3 w0.08: v3(38,18.8) 38,18.4 38.325,18.075 39.1,18.075 39.275,17.9 39.275,17.625 39.488,17.413 39.951,17.413 40.613,16.75 44.52,16.75 44.845,17.075 45.438,17.075 46.013,16.5 55.1,16.5 55.3,16.7 55.3,16.9 55.2,17 55.2,17.2 55.3,17.3 55.3,17.65 55.15,17.8 54.95,17.8 54.8,17.95 54.8,18.9 55.075,19.175 55.655,19.175 55.93,18.9 56.9,18.9 57.05,19.05 57.05,19.3 56.9,19.45 56.05,19.45 v4(56,19.4)
  L10 w0.08: v1@56.375,8.725 56.375,9.875 58.2,11.7 58.2,16 58,16.2 58,16.4 58.2,16.6 58.2,17.338 57.663,17.875 57.191,17.875 56.866,18.2 56.53,18.2 56.255,17.925 55.875,17.925 55.725,18.075 55.725,18.455 55.945,18.675 56.275,18.675 56.4,18.8 56.4,19.1 56.1,19.4 v4(56,19.4) 55.8,19.4 54.525,20.675 54.525,21.725 58.55,25.75 58.55,28.45 56.4,30.6 v1(56.4,30.7)
  L12 w0.093: U3.N7@53.6,7.4 53.375,7.625 53.375,8.05 53.65,8.325 56.025,8.325 v1(56.4,8.7) ; U5.N7@53.6,29.4 53.375,29.625 53.375,30.05 53.65,30.325 56.025,30.325 v1(56.4,30.7)
DRAM_A13: U1.AC17 U2.T3 U3.T3 U4.T3 U5.T3 | length 73.5
  L1 w0.093: U1.AC17@34.5,23.2 v2(34.9,22.8) ; U2.T3@56,7.4 56,7.55 56.25,7.8 56.5,7.8 57.2,7.1 57.5,7.1 58.125,7.725 58.625,7.725 v1(59.6,8.7) ; U4.T3@56,29.4 56,29.55 56.25,29.8 56.4,29.8 56.5,29.8 57.2,29.1 57.5,29.1 58.125,29.725 58.625,29.725 v1(59.6,30.7)
  L2 w0.1: v2(34.9,22.8) v3(35.2,22.5)
  L3 w0.08: v3(35.2,22.5) 35.275,22.425 35.855,22.425 36.03,22.6 39.599,22.6 40.749,21.45 44.22,21.45 44.569,21.101 46.7,21.101 47.426,20.375 49.158,20.375 49.258,20.475 51.058,20.475 51.483,20.9 52.8,20.9 52.9,21 54.37,21 54.745,20.625 55.055,20.625 55.5,21.07 55.5,22.33 55.945,22.775 57.025,22.775 57.8,22 59.4,22 59.8,21.6 v4(59.8,20)
  L10 w0.08: v1(59.6,8.7) 59.6,9.8 60.225,10.425 60.225,19 59.8,19.425 v4(59.8,20) 59.8,20.8 60,21 60.3,21 60.5,21.2 60.5,23.603 60.275,23.828 60.275,24.458 60.55,24.733 60.55,29.75 v1(59.6,30.7)
  L12 w0.093: U3.T3@56,10.6 57.6,10.6 57.95,10.25 58.78,10.25 59.6,9.43 v1(59.6,8.7) ; U5.T3@56,32.6 57.6,32.6 57.95,32.25 58.78,32.25 59.6,31.43 v1(59.6,30.7)
DRAM_A14: U1.AA12 U2.T7 U3.T7 U4.T7 U5.T7 | length 69.7
  L1 w0.093: v2(32.5,19.6) U1.AA12@32.9,19.2 ; U2.T7@56,10.6 57,10.6 58,9.6 v1(58,8.7) ; U4.T7@56,32.6 57,32.6 58,31.6 v1(58,30.7)
  L2 w0.1: v2(32.5,19.6) v3(32.8,19.3)
  L3 w0.08: v3(32.8,19.3) 32.7,19.2 32.7,17.53 32.875,17.355 32.875,16.225 33.075,16.025 36.062,16.025 36.262,15.825 36.738,15.825 36.913,16 55.426,16 56.675,17.249 56.675,17.7 57,18.025 57,18.6 57.25,18.85 57.25,19.25 v4(57.7,19.7)
  L10 w0.08: v1(58,8.7) 58,10.075 59.2,11.275 59.2,17.67 58.7,18.17 58.7,18.5 58.2,19 57.9,19 57.55,19.35 57.55,19.55 v4(57.7,19.7) 57.7,20.9 58,21.2 58,23.717 59.55,25.267 59.55,28.995 58,30.545 v1(58,30.7)
  L12 w0.093: U3.T7@56,7.4 56.2,7.2 56.45,7.2 56.775,7.525 57.342,7.525 57.504,7.687 57.504,7.996 57.633,8.125 57.942,8.125 58.175,8.358 58.175,8.525 v1(58,8.7) ; U5.T7@56,29.4 56.2,29.2 56.45,29.2 56.775,29.525 57.342,29.525 57.504,29.687 57.504,29.996 57.633,30.125 57.942,30.125 58.175,30.358 58.175,30.525 v1(58,30.7)
DRAM_A15: U1.Y12 U2.M7 U3.M7 U4.M7 U5.M7 | length 71.4
  L1 w0.093: v2(31.7,18.8) U1.Y12@32.1,19.2 ; v1(51.6,8.7) 51.6,9.6 51.8,9.8 52,9.8 U2.M7@52.8,10.6 ; v1(51.6,30.7) 51.6,31.6 51.8,31.8 52,31.8 U4.M7@52.8,32.6
  L2 w0.1: v2(31.7,18.8) v3(32,19.1)
  L3 w0.08: v3(32,19.1) 31.7,19.1 31.5,18.9 31.5,18.6 31.3,18.4 30.3,18.4 29.9,18 29.9,16.95 30.05,16.8 30.35,16.8 30.5,16.95 30.5,17.4 30.7,17.6 31.1,17.6 31.3,17.4 31.3,16.9 31.5,16.7 31.9,16.7 32.1,16.9 32.1,17.77 32.43,18.1 32.43,19.4 32.63,19.6 33.1,19.6 33.315,19.815 33.315,20.218 33.497,20.4 33.986,20.4 34.193,20.607 34.607,20.607 35.439,19.775 35.892,19.775 36.467,20.35 39.004,20.35 41.104,18.25 44.323,18.25 44.373,18.3 45.91,18.3 46.235,17.975 47.075,17.975 v4(47.2,18.1)
  L10 w0.08: v1(51.6,8.7) 51.6,9.6 52.825,10.825 52.825,12 52.54,12.285 52.54,13.385 51.1,14.825 50.845,14.825 50.625,15.045 50.625,15.45 49.575,16.5 47.8,16.5 47.65,16.65 47.65,16.85 47.8,17 48,17 48.15,17.15 48.15,19.1 48,19.25 47.75,19.25 47.6,19.1 47.6,18.2 47.5,18.1 v4(47.2,18.1) 47,18.3 47,19.25 47.3,19.55 47.3,22.25 47.75,22.7 48.817,22.7 50.142,24.025 50.321,24.025 50.721,24.425 51.205,24.425 51.375,24.595 51.375,25.555 52.8,26.98 52.8,29.161 51.6,30.361 v1(51.6,30.7)
  L12 w0.093: v1(51.6,8.7) 51.87,8.7 52.47,8.1 52.9,8.1 53.1,7.9 53.1,7.6 52.9,7.4 U3.M7@52.8,7.4 ; v1(51.6,30.7) 51.87,30.7 52.47,30.1 52.9,30.1 53.1,29.9 53.1,29.6 52.9,29.4 U5.M7@52.8,29.4
DRAM_CAS_B: U1.AE16 U2.K3 U3.K3 U4.K3 U5.K3 | length 70.7
  L1 w0.093: U1.AE16@36.1,22.4 v2(36.5,22.8) ; U2.K3@51.2,7.4 51.2,7.625 52,8.425 v1(52,9.3) ; U4.K3@51.2,29.4 51.2,29.625 52,30.425 v1(52,31.3)
  L2 w0.1: v3(36.2,23.1) v2(36.5,22.8)
  L3 w0.08: v3(36.2,23.1) 36.45,23.1 36.7,22.85 36.95,22.85 37.25,23.15 37.5,23.15 37.8,22.85 38.05,22.85 38.35,23.15 38.6,23.15 38.9,22.85 39.15,22.85 39.45,23.15 39.7,23.15 39.85,23 39.85,22.651 40,22.501 40.25,22.501 40.4,22.651 40.4,23 40.55,23.15 40.8,23.15 40.95,23 40.95,21.801 41.1,21.651 41.35,21.651 41.5,21.801 41.5,23 41.65,23.15 41.9,23.15 42.05,23 42.05,21.801 42.2,21.651 42.45,21.651 42.6,21.801 42.6,23 42.75,23.15 43,23.15 43.15,23 43.15,21.801 43.3,21.651 43.55,21.651 43.7,21.801 43.7,23 43.85,23.15 44.1,23.15 44.25,23 44.25,22.051 44.4,21.901 44.65,21.901 44.8,22.051 44.8,23 44.95,23.15 45.2,23.15 45.35,23 45.35,21.775 45.5,21.625 47.375,21.625 47.5,21.5 48.7,21.5 48.85,21.35 48.85,21.05 48.7,20.9 47.8,20.9 v4(47.7,21)
  L10 w0.08: v1(52,9.3) 52,9.6 53.575,11.175 53.575,11.955 53.33,12.2 53.07,12.2 52.825,12.445 52.825,13.45 51.375,14.9 51.375,15.355 51.155,15.575 50.85,15.575 49.675,16.75 48.9,16.75 48.4,17.25 48.4,19.2 48.15,19.45 47.85,19.45 47.7,19.6 47.7,19.85 47.85,20 48.2,20 48.35,20.15 48.35,20.4 48.2,20.55 47.9,20.55 47.7,20.75 v4(47.7,21) 47.7,22.3 47.85,22.45 48.1,22.45 48.25,22.3 48.25,21.35 48.4,21.2 48.65,21.2 48.8,21.35 48.8,22.35 50.275,23.825 50.404,23.825 50.729,24.15 51.263,24.15 51.625,24.512 51.625,25.475 53.175,27.025 53.355,27.025 53.575,27.245 53.575,28.355 53.13,28.8 53.13,29.17 52,30.3 v1(52,31.3)
  L12 w0.093: U3.K3@51.2,10.6 51.075,10.725 50.925,10.725 50.85,10.65 50.85,10.463 v1@52,9.313 ; U5.K3@51.2,32.6 51.075,32.725 50.925,32.725 50.85,32.65 50.85,32.463 v1@52,31.313
DRAM_CLK0_N: R2.1 U1.AE15 U4.K7 U5.K7 | length 64.1
  L1 w0.09: U1.AE15@36.1,21.6 36.2,21.7 36.5,21.7 36.9,22.1 37.1,22.1 37.2,22 37.2,21.75 37.3,21.65 37.5,21.65 37.6,21.75 37.6,22 37.7,22.1 38.65,22.1 39,22.45 39,22.65 39.196,22.846 39.792,22.846 39.988,22.65 39.988,21.546 40.331,21.204 41.133,21.204 41.476,21.546 41.476,22.65 41.672,22.846 42.268,22.846 42.464,22.65 42.464,21.546 42.807,21.204 43.609,21.204 43.952,21.546 43.952,22.65 44.148,22.846 44.744,22.846 44.94,22.65 44.94,21.546 45.283,21.204 46.085,21.204 46.428,21.546 46.428,22.65 46.624,22.846 47.22,22.846 47.416,22.65 47.416,21.746 47.759,21.404 48.561,21.404 48.904,21.746 48.904,23.796 47.977,24.723 47.5,25.2 47.5,26 47.973,26.473 49.073,26.473 49.35,26.196 49.35,26.004 49.176,25.83 48.922,25.83 48.67,25.578 48.67,25.03 v1(48.7,25) ; v1(48.3,31) 48.3,30.992 48.65,30.642 48.65,30.504 48.476,30.33 47.77,30.33 47.48,30.62 47.48,31.327 47.718,31.565 49.718,31.565 50.434,32.28 50.54,32.28 50.72,32.46 50.72,32.6 50.87,32.75 51.05,32.75 U4.K7@51.2,32.6
  L10 w0.085: v1(48.7,25) 48.22,25.48 48.22,25.916 49.304,27 50.12,27 50.368,27.248 50.368,28.352 48.3,30.42 v1(48.3,31) 48.3,31.196 49.104,32 49.9,32 50.487,32.587 50.487,34.387 52.3,36.2 v1(52.3,37.2)
  L12 w0.09: v1(48.3,31) 48.3,31.008 48.65,31.358 48.65,31.496 48.476,31.67 ; 48.476,31.67 47.77,31.67 47.48,31.381 47.48,30.673 47.768,30.385 49.768,30.385 50.434,29.72 50.54,29.72 50.72,29.54 50.72,29.4 50.87,29.25 51.05,29.25 U5.K7@51.2,29.4 ; R2.1@52.1,38 52.471,37.629 52.471,37.379 52.3,37.208 v1(52.3,37.2)
DRAM_CLK0_P: R2.2 U1.AD15 U4.J7 U5.J7 | length 64.1
  L1 w0.09: U1.AD15@35.3,21.6 35.612,21.6 35.962,21.95 36.396,21.95 36.796,22.35 38.546,22.35 38.75,22.554 38.75,22.754 39.093,23.096 39.895,23.096 40.238,22.754 40.238,21.65 40.434,21.454 41.03,21.454 41.226,21.65 41.226,22.754 41.569,23.096 42.371,23.096 42.714,22.754 42.714,21.65 42.91,21.454 43.506,21.454 43.702,21.65 43.702,22.754 44.045,23.096 44.847,23.096 45.19,22.754 45.19,21.65 45.386,21.454 45.982,21.454 46.178,21.65 46.178,22.754 46.521,23.096 47.323,23.096 47.666,22.754 47.666,21.85 47.862,21.654 48.458,21.654 48.654,21.85 48.654,23.692 47.25,25.096 47.25,26.104 47.87,26.723 49.177,26.723 49.6,26.3 49.6,25.9 v1(49.1,25.4) ; v1(48.9,31) 48.9,30.4 48.58,30.08 47.666,30.08 47.23,30.516 47.23,31.43 47.615,31.815 49.615,31.815 U4.J7@50.4,32.6
  L10 w0.085: v1(49.1,25.4) 49.037,25.463 48.633,25.463 48.5,25.596 48.5,25.8 49.42,26.72 50.236,26.72 50.648,27.132 50.648,28.468 48.58,30.536 48.58,30.626 48.9,30.946 v1(48.9,31) 48.9,31.4 49.22,31.72 50.016,31.72 50.767,32.471 50.767,34.271 52.58,36.084 52.58,36.68 52.9,37 v1(52.9,37.2)
  L12 w0.09: v1(48.9,31) 48.9,31.6 48.58,31.92 47.666,31.92 47.23,31.484 47.23,30.57 47.665,30.135 49.664,30.135 U5.J7@50.4,29.4 ; v1(52.9,37.2) 52.746,37.354 52.746,37.646 R2.2@53.1,38
DRAM_CLK1_N: R3.1 U1.AE14 U2.K7 U3.K7 | length 64.1
  L1 w0.09: U1.AE14@36.1,20.8 36.2,20.9 36.5,20.9 36.6,20.8 36.6,20.55 36.7,20.45 36.9,20.45 37,20.55 37,20.8 37.1,20.9 38.5,20.9 39.988,19.412 39.988,18.243 40.331,17.9 41.133,17.9 41.476,18.243 41.476,19.446 41.672,19.643 42.268,19.643 42.464,19.446 42.464,18.243 42.807,17.9 43.609,17.9 43.952,18.243 43.952,19.446 44.148,19.643 44.744,19.643 44.94,19.446 44.94,18.243 45.283,17.9 46.085,17.9 46.428,18.243 46.428,19.446 46.624,19.643 47.22,19.643 47.416,19.446 47.416,18.243 47.759,17.9 48.561,17.9 48.904,18.243 48.904,19.446 49.1,19.643 49.696,19.643 49.892,19.446 49.892,17.859 48.95,16.917 48.95,16.004 48.576,15.63 48.222,15.63 47.97,15.378 47.97,14.83 v1(48,14.8) ; v1(48.3,9) 48.3,8.992 48.65,8.642 48.65,8.504 48.476,8.33 47.77,8.33 47.48,8.62 47.48,9.327 47.718,9.565 49.718,9.565 50.434,10.28 50.54,10.28 50.72,10.46 50.72,10.6 50.87,10.75 51.05,10.75 U2.K7@51.2,10.6 ; R3.1@49.9,2 50.271,2.371 50.271,2.621 50.1,2.792 v1(50.1,2.8)
  L10 w0.085: v1(48,14.8) 48.063,14.737 48.467,14.737 48.6,14.604 48.6,14.2 49.832,12.968 50.152,12.968 50.368,12.752 50.368,11.263 49.567,10.463 49.567,10.048 49.252,9.732 48.944,9.732 48.3,9.089 v1(48.3,9) 48.3,8.92 48.52,8.7 48.52,8.484 49.102,7.902 50.298,7.902 50.92,7.28 50.92,4.616 50.22,3.916 50.22,2.92 v1(50.1,2.8)
  L12 w0.09: v1(48.3,9) 48.3,9.008 48.65,9.358 48.65,9.496 ; 48.646,9.501 48.476,9.67 47.77,9.67 47.48,9.381 47.48,8.673 47.768,8.386 49.768,8.386 50.434,7.72 50.54,7.72 50.72,7.54 50.72,7.4 50.87,7.25 51.05,7.25 U3.K7@51.2,7.4
DRAM_CLK1_P: R3.2 U1.AD14 U2.J7 U3.J7 | length 64
  L1 w0.09: U1.AD14@35.3,20.8 35.6,20.8 35.95,21.15 38.604,21.15 40.238,19.516 40.238,18.346 40.434,18.15 41.03,18.15 41.226,18.346 41.226,19.55 41.569,19.893 42.371,19.893 42.714,19.55 42.714,18.346 42.91,18.15 43.506,18.15 43.702,18.346 43.702,19.55 44.045,19.893 44.847,19.893 45.19,19.55 45.19,18.346 45.386,18.15 45.982,18.15 46.178,18.346 46.178,19.55 46.521,19.893 47.323,19.893 47.666,19.55 47.666,18.346 47.862,18.15 48.458,18.15 48.654,18.346 48.654,19.55 48.997,19.893 49.799,19.893 50.142,19.55 50.142,17.755 49.2,16.813 49.2,15.9 48.5,15.2 v1(48.4,15.2) ; v1(48.9,9) 48.9,8.4 48.58,8.08 47.666,8.08 47.23,8.516 47.23,9.43 47.615,9.815 49.615,9.815 U2.J7@50.4,10.6 ; v1(50.7,2.8) 50.546,2.646 50.546,2.354 R3.2@50.9,2
  L10 w0.085: v1(48.4,15.2) 48.88,14.72 48.88,14.316 49.948,13.248 50.268,13.248 50.648,12.868 50.648,11.148 49.847,10.347 49.847,9.932 49.368,9.452 49.06,9.452 48.9,9.293 v1(48.9,9) 48.8,8.9 48.8,8.6 49.218,8.182 50.414,8.182 51.2,7.396 51.2,4.5 50.5,3.8 50.5,3 v1(50.7,2.8)
  L12 w0.09: v1(48.9,9) 48.9,9.6 48.58,9.92 47.666,9.92 47.23,9.484 47.23,8.57 47.665,8.136 49.664,8.136 U3.J7@50.4,7.4
DRAM_CS0_B: U1.Y16 U2.L2 U3.L2 U4.L2 U5.L2 | length 73.8
  L1 w0.093: v2(31.7,22.8) U1.Y16@32.1,22.4 ; U2.L2@52,6.6 52.15,6.6 52.275,6.725 52.275,6.9 52.1,7.075 51.775,7.075 51.6,7.25 51.6,7.675 51.946,8.021 52.171,8.021 52.4,8.25 v1(52.4,8.7) ; U4.L2@52,28.6 52.15,28.6 52.275,28.725 52.275,28.9 52.1,29.075 51.775,29.075 51.6,29.25 51.6,29.675 51.946,30.021 52.171,30.021 52.4,30.25 v1(52.4,30.7)
  L2 w0.1: v3(31.4,22.5) v2(31.7,22.8)
  L3 w0.08: v3(31.4,22.5) 31.715,22.815 32.415,22.815 32.9,23.3 32.9,24.53 33.145,24.775 36.655,24.775 37.28,24.15 50.4,24.15 50.55,24 50.55,23.75 50.4,23.6 50,23.6 49.85,23.45 49.85,23.2 50,23.05 50.4,23.05 50.55,22.9 50.55,22.65 50.4,22.5 50,22.5 49.85,22.35 49.85,22.1 50,21.95 50.35,21.95 50.5,21.8 50.5,21.55 50.35,21.4 50.1,21.4 v4(50,21.3)
  L10 w0.08: v1(52.4,8.7) 52.4,9.6 53.8,11 53.8,12.2 53.625,12.375 53.625,13 51.625,15 51.625,15.388 51.238,15.775 51,15.775 49.775,17 49.1,17 48.65,17.45 48.65,20.5 49.15,21 49.9,21 50,21.1 v4(50,21.3) 50,21.45 49.9,21.55 49.2,21.55 49.05,21.7 49.05,21.95 49.2,22.1 50.35,22.1 50.5,22.25 50.5,22.5 50.35,22.65 50,22.65 49.85,22.8 49.85,22.988 50.762,23.9 51.346,23.9 51.875,24.429 51.875,25.262 53.638,27.025 54.155,27.025 54.375,27.245 54.375,27.555 54.595,27.775 54.75,27.775 54.9,27.925 54.9,28.175 54.75,28.325 54.475,28.325 54.25,28.1 54,28.1 53.85,28.25 53.85,29.233 53.391,29.691 52.909,29.691 52.741,29.859 52.741,30.341 52.4,30.683 v1(52.4,30.7)
  L12 w0.093: U3.L2@52,11.4 51.6,11 51.6,10.25 52.4,9.45 v1(52.4,8.7) ; U5.L2@52,33.4 51.6,33 51.6,32.25 52.4,31.45 v1(52.4,30.7)
DRAM_D0: U1.AD2 U2.D7 | length 17.3
  L1 w0.093: v2(34.9,10.8) U1.AD2@35.3,11.2 ; v3(46.4,10.6) v2(46.8,11)
  L2 w0.1: v2(34.9,10.8) v3(35.2,11.1) ; v3(46.4,10.6) v2(46.8,11)
  L3 w0.08: v3(35.2,11.1) 35,11.3 35,12.513 35.472,12.985 36.801,12.985 37.153,12.633 39.248,12.633 39.657,13.042 42.608,13.042 43,12.65 43,12.2 43.225,11.975 43.225,11.645 43.445,11.425 44.012,11.425 44.287,11.7 44.903,11.7 45.2,11.403 45.2,11.2 45.5,10.9 46.1,10.9 v3(46.4,10.6)
DRAM_D1: U1.AE2 U2.B8 | length 17.3
  L1 w0.093: v2(35.7,10.8) U1.AE2@36.1,11.2 ; v2(44.4,11.8) v3(44.8,11.4)
  L2 w0.1: v2(35.7,10.8) v3(36,11.1) ; v2(44.4,11.8) v3(44.8,11.4)
  L3 w0.08: v3(36,11.1) 36,10.8 35.9,10.7 35.7,10.7 35.485,10.915 35.485,11.385 35.6,11.5 35.985,11.5 36.1,11.615 36.1,11.867 35.967,12 35.4,12 35.225,12.175 35.225,12.455 35.555,12.785 36.718,12.785 37.136,12.367 39.382,12.367 39.8,12.785 40.315,12.785 40.5,12.6 40.7,12.6 40.885,12.785 42.532,12.785 42.8,12.517 42.8,11.7 43.338,11.162 44.032,11.162 44.37,11.5 44.7,11.5 v3(44.8,11.4)
DRAM_D2: U1.AC4 U2.C8 | length 17.3
  L1 w0.093: U1.AC4@34.5,12.8 v2(34.9,12.4) ; v2(45.2,11.8) v3(45.6,11.4)
  L2 w0.1: v3(34.6,12.1) v2(34.9,12.4) ; v2(45.2,11.8) v3(45.6,11.4)
  L3 w0.08: v3(34.6,12.1) 34.6,12.623 35.162,13.185 36.884,13.185 37.169,12.9 39.2,12.9 39.6,13.3 42.9,13.3 43.2,13 43.2,12.4 43.4,12.2 43.75,12.2 44,11.95 45.55,11.95 45.8,12.2 46.2,12.2 46.425,11.975 46.425,11.695 46.13,11.4 v3(45.6,11.4)
DRAM_D3: U1.AA5 U2.A3 | length 17.3
  L1 w0.093: U1.AA5@32.9,13.6 v2(33.3,13.2) ; v2(43.6,7) U2.A3@44,7.4
  L2 w0.1: v2(33.3,13.2) v3(33.6,12.9) ; v3(43.2,6.6) v2(43.6,7)
  L3 w0.08: v3(33.6,12.9) 33.6,12.503 33.315,12.218 33.315,11.572 34.102,10.785 34.518,10.785 34.7,10.603 34.7,10.313 34.975,10.038 34.975,9.768 37,7.743 37,7.183 37.783,6.4 38.5,6.4 39.2,5.7 42.9,5.7 43.3,6.1 43.3,6.5 v3(43.2,6.6)
DRAM_D4: U1.AC1 U2.C2 | length 17.3
  L1 w0.093: v2(34.1,10.8) U1.AC1@34.5,10.4 ; v2(45.2,6.2) v3(45.6,6.6)
  L2 w0.1: v2(34.1,10.8) v3(34.4,10.5) ; v2(45.2,6.2) v3(45.6,6.6)
  L3 w0.08: v3(34.4,10.5) 34.4,10.33 34.775,9.955 34.775,9.593 36.7,7.668 36.7,7.2 37.8,6.1 38.4,6.1 39.1,5.4 43.07,5.4 43.67,6 43.9,6 44.125,5.775 44.575,5.775 44.775,5.975 44.775,6.675 44.9,6.8 45.5,6.8 45.6,6.7 v3(45.6,6.6)
DRAM_D5: U1.AD1 U2.C3 | length 17.3
  L1 w0.093: U1.AD1@35.3,10.4 v2(35.7,10) ; v2(45.2,7) v3(45.6,7.4)
  L2 w0.1: v3(35.4,10.3) v2(35.7,10) ; v2(45.2,7) v3(45.6,7.4)
  L3 w0.08: v3(35.4,10.3) 35.4,10.2 36.9,8.7 38.613,8.7 39.3,8.013 39.3,6.6 39.6,6.3 39.9,6.3 40.05,6.45 40.05,6.65 40.2,6.8 40.5,6.8 40.65,6.65 40.65,6.35 40.8,6.2 41.1,6.2 41.25,6.35 41.25,6.65 41.4,6.8 41.7,6.8 41.85,6.65 41.85,6.35 42,6.2 42.2,6.2 42.35,6.35 42.35,6.55 43.1,7.3 44.17,7.3 44.245,7.375 44.555,7.375 44.88,7.05 45.25,7.05 v3(45.6,7.4)
DRAM_D6: U1.AB4 U2.A2 | length 17.3
  L1 w0.093: v2(33.3,12.4) U1.AB4@33.7,12.8 ; v2(43.6,6.2) v3(44,6.6)
  L2 w0.1: v2(33.3,12.4) v3(33.6,12.1) ; v2(43.6,6.2) v3(44,6.6)
  L3 w0.08: v3(33.6,12.1) 33.6,11.57 33.945,11.225 34.163,11.225 34.403,10.985 34.601,10.985 34.9,10.686 34.9,10.396 35.175,10.121 35.175,10.025 36.8,8.4 38.5,8.4 39,7.9 39,6.4 39.45,5.95 42.575,5.95 42.8,6.175 42.8,6.603 43.197,7 43.6,7 v3(44,6.6)
DRAM_D7: U1.AE4 U2.A7 | length 17.3
  L1 w0.093: U1.AE4@36.1,12.8 v2(36.9,12.8) ; v2(43.6,11) v3(44,10.6)
  L2 w0.1: v3(36.6,12.5) v2(36.9,12.8) ; v2(43.6,11) v3(44,10.6)
  L3 w0.08: v3(36.6,12.5) 36.275,12.5 36.125,12.35 36.125,12.175 36.25,12.05 38.85,12.05 39,11.9 39,11.67 39.245,11.425 39.555,11.425 39.8,11.67 39.8,12.4 39.95,12.55 40.2,12.55 40.35,12.4 40.35,11.57 40.5,11.42 40.75,11.42 40.9,11.57 40.9,12.4 41.05,12.55 41.3,12.55 41.45,12.4 41.45,11.67 41.6,11.52 41.85,11.52 42,11.67 42,12.43 42.15,12.58 42.4,12.58 42.55,12.43 42.55,11.45 43.1,10.9 43.7,10.9 v3(44,10.6)
DRAM_D8: U1.AD5 U2.E3 | length 27.6
  L1 w0.093: U1.AD5@35.3,13.6 v2(35.7,13.2) ; v2(46.8,7) v3(47.2,7.4)
  L2 w0.1: v3(35.4,13.5) v2(35.7,13.2) ; v2(46.8,7) v3(47.2,7.4)
  L3 w0.08: v3(35.4,13.5) 35.003,13.5 34.503,13 34.085,13 33.9,13.185 33.482,13.185 33.3,13.003 33.3,12.7 33,12.4 33,11.1 34.025,10.075 34.025,9.375 38.7,4.7 44.6,4.7 44.8,4.9 44.8,5.6 45,5.8 45.4,5.8 45.6,5.6 45.6,5.1 45.837,4.863 46.163,4.863 46.4,5.1 46.4,6.4 46.6,6.6 47,6.6 47.2,6.8 v3(47.2,7.4)
DRAM_D9: U1.AE5 U2.F7 | length 27.6
  L1 w0.093: U1.AE5@36.1,13.6 v2(36.5,13.2) ; v3(48,10.6) v2(48.4,11)
  L2 w0.1: v3(36.2,13.5) v2(36.5,13.2) ; v3(48,10.6) v2(48.4,11)
  L3 w0.08: v3(36.2,13.5) 35.9,13.5 35.75,13.65 35.75,13.85 35.9,14 36.3,14 36.7,13.6 36.9,13.6 37.2,13.3 38.7,13.3 39.2,13.8 43.5,13.8 43.7,13.6 43.7,13.08 43.85,12.93 44.1,12.93 44.25,13.08 44.25,13.6 44.4,13.75 44.65,13.75 44.8,13.6 44.8,12.4 45,12.2 45.4,12.2 45.6,12.4 45.6,13.6 45.75,13.75 46,13.75 46.15,13.6 46.15,13.08 46.3,12.93 46.55,12.93 46.7,13.08 46.7,13.6 46.85,13.75 47.05,13.75 47.225,13.575 47.225,11.525 47.1,11.4 46.7,11.4 46.55,11.25 46.55,10.938 46.8,10.688 46.8,10.544 47.029,10.315 48.515,10.315 48.7,10.5 48.7,10.9 48.5,11.1 48.1,11.1 48,11 v3(48,10.6)
DRAM_D10: U1.AA6 U2.G2 | length 27.6
  L1 w0.093: U1.AA6@32.9,14.4 v2(33.3,14) ; v2(48.4,6.2) U2.G2@48.8,6.6
  L2 w0.1: v3(33,14.3) v2(33.3,14) ; v2(48.4,6.2) v3(48.8,5.8)
  L3 w0.08: v3(33,14.3) 32.125,13.425 32.125,10.425 32.3,10.25 32.68,10.25 33.275,9.655 33.275,8.925 38.3,3.9 48,3.9 48.4,4.3 48.4,4.85 48.8,5.25 v3(48.8,5.8)
DRAM_D11: U1.AE7 U2.H7 | length 27.6
  L1 w0.093: U1.AE7@36.1,15.2 v2(36.5,14.8) ; v2(49.2,11) v3(49.6,10.6)
  L2 w0.1: v2(36.5,14.8) v3(36.8,15.1) ; v2(49.2,11) v3(49.6,10.6)
  L3 w0.08: v3(36.8,15.1) 36.8,14.97 37.545,14.225 38.055,14.225 38.63,14.8 47.37,14.8 47.77,14.4 48.13,14.4 48.53,14.8 52,14.8 52.8,14 52.8,12 52.6,11.8 52.1,11.8 51.95,11.65 51.95,11.35 52.1,11.2 52.8,11.2 52.95,11.05 52.95,10.75 52.8,10.6 v3(49.6,10.6)
DRAM_D12: U1.AB5 U2.H3 | length 27.6
  L1 w0.093: U1.AB5@33.7,13.6 v2(34.1,13.2) ; v2(49.2,7.8) v3(49.6,7.4)
  L2 w0.1: v3(33.8,13.5) v2(34.1,13.2) ; v2(49.2,7.8) v3(49.6,7.4)
  L3 w0.08: v3(33.8,13.5) 33.464,13.5 33.075,13.111 33.075,12.868 32.708,12.501 32.708,10.992 33.758,9.942 33.758,9.234 38.559,4.433 46.364,4.433 47.175,5.245 47.175,6.178 47.882,6.885 48.315,6.885 48.575,6.625 49.355,6.625 49.6,6.87 v3(49.6,7.4)
DRAM_D13: U1.AC5 U2.F2 | length 27.6
  L1 w0.093: U1.AC5@34.5,13.6 v2(34.9,13.2) ; v2(47.6,6.2) v3(48,6.6)
  L2 w0.1: v3(34.6,13.5) v2(34.9,13.2) ; v2(47.6,6.2) v3(48,6.6)
  L3 w0.08: v3(34.6,13.5) 34.368,13.5 34.083,13.785 33.365,13.785 32.875,13.295 32.875,13.045 32.417,12.586 32.417,10.918 33.5,9.834 33.5,9.118 38.451,4.167 47.367,4.167 47.6,4.4 47.6,4.87 48,5.27 v3(48,6.6)
DRAM_D14: U1.AB6 U2.F8 | length 27.6
  L1 w0.093: U1.AB6@33.7,14.4 v2(34.1,14) ; v2(47.6,11.8) v3(48,11.4)
  L2 w0.1: v3(33.8,14.3) v2(34.1,14) ; v2(47.6,11.8) v3(48,11.4)
  L3 w0.08: v3(33.8,14.3) 34.13,14.3 34.43,14.6 34.703,14.6 34.885,14.418 34.885,14.315 34.985,14.215 35.318,14.215 35.528,14.425 36.575,14.425 37,14 37.134,14 37.372,13.762 38.362,13.762 38.9,14.3 47.23,14.3 47.664,13.867 48.367,13.867 48.8,14.3 51.511,14.3 51.945,13.866 51.945,13.3 51.745,13.1 51.4,13.1 51.2,12.9 51.2,12.5 50.925,12.225 48.295,12.225 48,11.93 v3(48,11.4)
DRAM_D15: U1.AC7 U2.H8 | length 27.6
  L1 w0.093: U1.AC7@34.5,15.2 v2(34.9,14.8) ; v3(49.6,11.4) v2(50,11)
  L2 w0.1: v2(34.9,14.8) v3(35.2,14.5) ; v3(49.6,11.4) v2(50,11)
  L3 w0.08: v3(35.2,14.5) 35.2,14.85 35.525,15.175 35.893,15.175 36.368,14.7 36.717,14.7 37.423,13.994 38.194,13.994 38.75,14.55 47.3,14.55 47.717,14.133 48.233,14.133 48.65,14.55 51.85,14.55 52.5,13.9 52.5,12.3 52.3,12.1 52.1,12.1 51.8,12.4 51.5,12.4 51.198,12.098 51.198,10.998 51.05,10.85 50.75,10.85 50.6,11 50.6,11.2 50.4,11.4 v3(49.6,11.4)
DRAM_D16: U1.AB7 U3.E3 | length 28.5
  L1 w0.093: U1.AB7@33.7,15.2 v1(34.1,14.8)
  L10 w0.08: v1(34.1,14.8) 34.1,15 33.725,15.375 33.725,16.505 33.455,16.775 33.195,16.775 32.925,17.045 32.925,17.45 33.075,17.6 33.7,17.6 33.85,17.75 33.85,18 33.7,18.15 32.55,18.15 32.4,18.3 32.4,18.55 32.55,18.7 33.45,18.7 33.975,19.225 34.255,19.225 34.415,19.385 37.04,19.385 37.15,19.275 39.219,19.275 39.543,18.95 39.543,18.432 39.937,18.038 41.236,18.038 43.775,15.499 43.775,14.925 44.113,14.587 44.913,14.587 46.375,13.125 46.375,11.425 v6(47.2,10.6)
  L11 w0.1: v6(47.2,10.6) v5(47.6,11)
  L12 w0.093: v6(47.2,10.6) v5(47.6,11)
DRAM_D17: U1.AA8 U3.F8 | length 28.5
  L1 w0.093: U1.AA8@32.9,16 v1(33.3,15.6)
  L10 w0.08: v1(33.3,15.6) 33.525,15.375 33.525,15.117 33.7,14.942 33.7,14.183 34.675,13.208 34.675,11.725 35.9,10.5 35.9,9.783 36.8,8.883 36.8,6.9 40.2,3.5 47.7,3.5 48.05,3.85 48.05,4.25 47.9,4.4 47.7,4.4 47.55,4.55 47.55,4.85 47.7,5 48.53,5 48.775,5.245 48.775,5.555 48.53,5.8 v6(48,5.8)
  L11 w0.1: v5(47.6,6.2) v6(48,5.8)
  L12 w0.093: v5(47.6,6.2) U3.F8@48,6.6
DRAM_D18: U1.AB9 U3.H7 | length 28.5
  L1 w0.093: U1.AB9@33.7,16.8 v1(34.1,16.4)
  L10 w0.08: v1(34.1,16.4) 34.1,16.13 34.475,15.755 34.475,15.4 34.7,15.175 34.7,14.45 34.55,14.3 34.55,14 35.1,13.45 35.1,11.93 39.387,7.643 39.387,6.913 39.6,6.7 39.6,4.9 40.25,4.25 40.55,4.25 40.7,4.4 40.7,4.6 40.85,4.75 41.15,4.75 41.3,4.6 41.3,4.267 41.467,4.1 45.7,4.1 46.4,4.8 46.4,5.53 46.695,5.825 46.955,5.825 47.175,6.045 47.175,6.178 47.997,7 48.67,7 49.07,7.4 v6(49.6,7.4)
  L11 w0.1: v5(49.2,7.8) v6(49.6,7.4)
  L12 w0.093: v5(49.2,7.8) v6(49.6,7.4)
DRAM_D19: U1.Y9 U3.H3 | length 28.5
  L1 w0.093: v1(31.7,17.2) U1.Y9@32.1,16.8
  L10 w0.08: v1(31.7,17.2) 31.7,19.5 31.9,19.7 32.859,19.7 33.334,20.175 34.625,20.175 34.717,20.083 35.125,20.083 35.424,19.785 40.346,19.785 44.8,15.33 44.939,15.33 45.67,14.6 46.4,14.6 46.6,14.4 46.6,14.199 46.488,14.087 46.488,13.885 46.688,13.685 46.89,13.685 47.101,13.897 47.303,13.897 47.503,13.697 47.503,13.28 48.025,12.758 48.025,12.025 47.6,11.6 47.6,11.2 47.8,11 48.9,11 49.3,11.4 v6(49.6,11.4)
  L11 w0.1: v5(49.2,11) v6(49.6,11.4)
  L12 w0.093: v5(49.2,11) U3.H3@49.6,10.6
DRAM_D20: U1.Y7 U3.H8 | length 28.5
  L1 w0.093: U1.Y7@32.1,15.2 v1(32.5,14.8)
  L10 w0.08: v1(32.5,14.8) 32.709,14.8 34.475,13.034 34.475,11.642 35.7,10.417 35.7,9.7 36.5,8.9 36.5,6.8 40.1,3.2 48,3.2 49,4.2 49,4.5 49.6,5.1 v6(49.6,6.6)
  L11 w0.1: v6(49.6,6.6) v5(50,7)
  L12 w0.093: v6(49.6,6.6) v5(50,7)
DRAM_D21: U1.Y8 U3.G2 | length 28.6
  L1 w0.093: U1.Y8@32.1,16 v1(32.5,15.6)
  L10 w0.08: v1(32.5,15.6) 32.5,15.73 31.3,16.93 31.3,19.5 31.8,20 32.876,20 33.251,20.375 35.195,20.375 35.545,20.025 40.475,20.025 44.925,15.575 45.855,15.575 46.1,15.33 46.1,15.15 46.425,14.825 46.705,14.825 48.8,12.73 v6(48.8,11.4)
  L11 w0.1: v5(48.4,11) v6(48.8,11.4)
  L12 w0.093: v5(48.4,11) v6(48.8,11.4)
DRAM_D22: U1.AC8 U3.F7 | length 28.5
  L1 w0.093: U1.AC8@34.5,16 v1(34.9,15.6)
  L10 w0.08: v1(34.9,15.6) 34.9,14.2 35.3,13.8 35.3,12.1 39.7,7.7 39.7,7.1 39.9,6.9 39.9,5 40.05,4.85 40.35,4.85 40.8,5.3 41.6,5.3 41.75,5.15 41.75,4.55 41.9,4.4 42.15,4.4 42.3,4.55 42.3,5.15 42.45,5.3 42.7,5.3 42.85,5.15 42.85,4.55 43,4.4 43.25,4.4 43.4,4.55 43.4,4.85 43.55,5 43.8,5 43.95,4.85 43.95,4.55 44.1,4.4 44.35,4.4 44.5,4.55 44.5,4.85 44.65,5 44.9,5 45.05,4.85 45.05,4.55 45.2,4.4 45.425,4.4 45.575,4.55 45.575,5.505 45.895,5.825 46.155,5.825 46.425,6.095 46.425,6.355 46.67,6.6 47.1,6.6 47.7,7.2 47.8,7.2 v6(48,7.4)
  L11 w0.1: v6(48,7.4) v5(48.4,7)
  L12 w0.093: v6(48,7.4) v5(48.4,7)
DRAM_D23: U1.AA9 U3.F2 | length 28.6
  L1 w0.093: U1.AA9@32.9,16.8 v1(33.3,16.4)
  L10 w0.08: v1(33.3,16.4) 33.3,16.1 33.2,16 32.6,16 32.125,16.475 32.125,17.5 32,17.625 32,19.2 32.2,19.4 32.5,19.4 32.8,19.1 33.3,19.1 33.5,19.3 33.5,19.775 33.7,19.975 34.4,19.975 34.6,19.775 35.117,19.775 35.307,19.585 37.123,19.585 37.183,19.525 40.236,19.525 40.553,19.208 40.553,19.013 40.378,18.838 40.005,18.838 39.855,18.688 39.855,18.438 40.03,18.263 41.38,18.263 44.025,15.619 44.025,15.045 44.245,14.825 45.105,14.825 47.2,12.73 v6(47.2,11.4)
  L11 w0.1: v6(47.2,11.4) v5(47.6,11.8)
  L12 w0.093: v5(47.6,11.8) U3.F2@48,11.4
